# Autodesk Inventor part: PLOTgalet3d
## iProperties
Author: ajt
Created: 2001-10
Part Number: PLOTgalet3d
Material: Par défaut
Document SubType Name: Proxy Part
Designer: ajt
Control State: 0
Master: False
Checked Out: False
PropertySet Name: Design Tracking Control
Shininess: 21.0
PropertySet Name: _Private Model Information
Length Units: 11269
Angle Units: 11283
Time Units: 11279
Mass Units: 11290
Length Display Precision: 3
Angle Display Precision: 2
Compacted: False
Density: 0.0
Volumn: 0.0
Area: 0.0
PropertySet Name: Model Information
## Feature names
1. LinkedPart1
